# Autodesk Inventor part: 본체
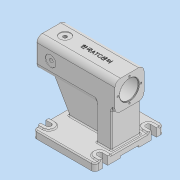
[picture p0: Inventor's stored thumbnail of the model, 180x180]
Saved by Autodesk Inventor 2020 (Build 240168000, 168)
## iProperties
Created: 2024-07
Part Number: 본체
Material: 일반
Document SubType Name: Modeling
Designer: oem
Density: 1 g/cm^3
Appearance: 기본값
Author: oem
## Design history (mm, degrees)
sketch "스케치1"
  geometry: L1 (85, -95)-(-85, -95); L2 (-85, -95)-(-85, 95); L3 (-85, 95)-(85, 95); L4 (85, 95)-(85, -95); 3 further points
  constraints: 8 end point, 2 midpoint, 2 parallel, 1 horizontal, 1 horizontal alignment, 1 perpendicular, 1 vertical alignment
  dimensions: "d0" = 170 distance of L1.start L1.end; "d1" = 190 distance of L1.end L2.end
extrude "돌출1" new body sketch "스케치1" distance "d2" = 20; taper "d3" = 0 deg
sketch "스케치2"
  geometry: L1 (0, 0)-(190, 0) reference; L2 (55, 190)-(135, 190); L3 (135, 190)-(135, 110); L4 (135, 110)-(55, 110); L5 (55, 110)-(55, 190); 4 further points
  constraints: 8 end point, 3 midpoint, 2 parallel, 1 horizontal, 1 perpendicular, 1 vertical alignment
  dimensions: "d4" = 80 distance of L2.end L3.end; "d5" = 80 distance of L2.start L2.end; "d6" = 150 distance from line of L1 point (55, 150)
extrude "돌출2" join sketch "스케치2" distance "d7" = 217; taper "d8" = 0 deg
sketch "스케치3"
  geometry: L1 (85, -95)-(85, 95) reference; L2 (35, -40)-(75, -40); L3 (75, -40)-(75, 40); L4 (75, 40)-(35, 40); L5 (35, 40)-(35, -40); 2 further points
  constraints: 8 end point, 2 parallel, 1 horizontal, 1 horizontal alignment, 1 midpoint, 1 perpendicular
  dimensions: "d9" = 40 distance of L3.end L4.end; "d10" = 80 distance of L2.end L3.end; "d11" = 10 distance between parallel lines of L1 L3
extrude "돌출3" join sketch "스케치3" stored distance "d12" = 217; taper "d13" = 0 deg
node "작업 평면1"
sketch "스케치4"
  geometry: L1 (-50, 0)-(-217, 0) reference; L2 (-202, 0)-(-150.038, -90); L3 (0, -90)-(-170, -90) reference; L4 (-10, -90)-(-10, 0) reference; L5 (-50, -90)-(-10, -90) reference; L6 (-50, -90)-(-50, 0) reference; L7 (-50, 0)-(-217, 0) reference; L8 (-217, 80)-(-217, 0) reference; L9 (0, 80)-(-217, 80) reference; L10 (0, 0)-(0, 80) reference; L11 (0, 0)-(-10, 0) reference; L12 (0, -110)-(-170, -110) reference; L13 (-170, -110)-(-170, -90) reference; L14 (0, -90)-(-170, -90) reference; L15 (0, -110)-(0, -90) reference; 3 further points
  constraints: 2 end point, 2 point on line
  dimensions: "d15" = 15 distance of L1.end L2.start; "d16" = 120 deg angle of L3 L2
extrude "돌출4" join sketch "스케치4" stored distance "d17" = 30; taper "d18" = 0 deg
sketch "스케치5"
  geometry: L1 (-132, 150)-(85, 150); L2 (85, 176)-(-127, 176); L3 (-127, 176)-(-127, 170.5); L4 (-127, 170.5)-(-132, 170.5); L5 (-132, 190)-(-132, 110) reference; L6 (85, 110)-(85, 190) reference; 1 further point
  constraints: 8 end point, 2 midpoint, 2 perpendicular, 2 point on line, 1 horizontal
  dimensions: "d22" = 212 distance of L2.start L2.end; "d25" = 41 diameter of L4 L1; "d26" = 52 diameter of L2 L1
revolve "회전1" sketch "스케치5" stored, may be unused: angle "d27" = 90 deg
sketch "스케치6"
  geometry: L1 (0, 0)-(190, 0) reference; L2 (70, 0)-(120, 0); L3 (120, 0)-(120, 5); L4 (120, 5)-(70, 5); L5 (70, 5)-(70, 0); 5 further points
  constraints: 8 end point, 2 midpoint, 2 parallel, 1 collinear, 1 horizontal, 1 perpendicular, 1 vertical alignment
  dimensions: "d31" = 50 distance of L2.start L2.end; "d32" = 5 distance of L4.end L2.start
extrude "돌출5" cut sketch "스케치6" distance "d33" = 184.25; taper "d34" = 0 deg
sketch "스케치7" dims "d37" = 30
  geometry: L1 (85, -95)-(85, 95) reference; L2 (70, -67)-(70, 67); L3 (85, -82)-(70, -82); L4 (85, 52)-(70, 52); L5 (85, -52)-(70, -52); L6 (85, 82)-(70, 82); L7 (-85, -95)-(85, -95) reference; L8 (0, -95)-(0, 115.42); L9 (-75, 40)-(-75, -40); L10 (-70, -67)-(-70, 67); L11 (-85, -95)-(-85, 95); L12 (-85, -52)-(-70, -52); L13 (-85, -82)-(-70, -82); L14 (-85, 52)-(-70, 52); L15 (-85, 82)-(-70, 82); A1 r 15 centre (70, -67) between (70, -82) and (70, -52); A2 r 15 centre (-70, -67) between (-70, -82) and (-70, -52); 9 further points
  constraints: 26 end point, 14 symmetric about line, 10 point on line, 6 horizontal, 4 point on circle, 3 midpoint, 2 centre point, 2 tangent, 2 vertical, 1 horizontal alignment, 7 other
  dimensions: "d35" = 30 diameter of A1; "d36" = 15 distance from line of L1 L2.start; "d38" = 15 distance from line of L1 L2.end; "d39" = 134 distance of L2.start L2.end
extrude "돌출6" join sketch "스케치7" distance "d40" = 3; taper "d41" = 0 deg
sketch "스케치8"
  geometry: L1 (85, 82)-(70, 82) reference; L2 (70, 52)-(85, 52) reference; L3 (85, 52)-(85, 82) reference; L4 (85, 60)-(70, 60); L5 (70, 74)-(85, 74); L6 (70, -82)-(85, -82) reference; L7 (70, -82)-(85, -82) reference; L8 (85, -82)-(85, -52) reference; L9 (85, -52)-(70, -52) reference; L10 (70, -74)-(85, -74); L11 (85, -60)-(70, -60); L12 (-85, -95)-(85, -95) reference; L13 (0, -95)-(0, 108.744); L14 (-85, 82)-(-70, 82); L15 (-70, 52)-(-85, 52); L16 (-85, 60)-(-70, 60); L17 (-70, 74)-(-85, 74); L18 (-85, 52)-(-85, 82); L19 (-85, -52)-(-70, -52); L20 (-85, -60)-(-70, -60); L21 (-70, -74)-(-85, -74); L22 (-85, -82)-(-85, -52); L23 (-70, -82)-(-85, -82); L24 (-70, -82)-(-85, -82); A1 r 15 centre (70, 67) between (70, 82) and (70, 52) reference; A2 r 7 centre (70, 67) between (70, 74) and (70, 60); A3 r 15 centre (70, -67) between (70, -52) and (70, -82) reference; A4 r 15 centre (70, -67) between (70, -52) and (70, -82) reference; A5 r 7 centre (70, -67) between (70, -60) and (70, -74); A6 r 15 centre (-70, 67) between (-70, 52) and (-70, 82); A7 r 7 centre (-70, 67) between (-70, 60) and (-70, 74); A8 r 7 centre (-70, -67) between (-70, -74) and (-70, -60); A9 r 15 centre (-70, -67) between (-70, -82) and (-70, -52); A10 r 15 centre (-70, -67) between (-70, -82) and (-70, -52); 1 further point
  constraints: 32 end point, 22 symmetric about line, 14 point on circle, 8 point on line, 7 centre point, 1 midpoint, 1 perpendicular, 1 vertical, 8 other
  dimensions: "d42" = 14 distance between parallel lines of L5 L4; "d43" = 14 distance of L10.end L11.start
extrude "돌출7" cut sketch "스케치8" stored distance "d44" = 3; taper "d45" = 0 deg
sketch "스케치9"
  geometry: L1 (0, 80)-(0, 0) reference; L2 (0, 40)-(-177, 40); 2 further points
  constraints: 2 end point, 2 midpoint, 1 coincident, 1 horizontal
  dimensions: "d46" = 177 distance of L2.start L2.end
hole "구멍1" sketch "스케치9" at (-177, 40) diameter "d47" = 10.106; stored, may be unused: countersink angle "d51" = 90 deg, drill point angle "d53" = 118 deg; dims "d48" = 24, "d49" = 30, "d50" = 2, "d52" = 32.3
sketch "스케치10"
  geometry: L1 (0, -12)-(0, 92) reference; L2 (0, 40)-(-177, 40); 1 further point
  constraints: 2 end point, 1 horizontal, 1 midpoint
  dimensions: "d54" = 177 distance of L2.start L2.end
hole "구멍2" sketch "스케치10" at (-177, 40) diameter "d55" = 10.106; stored, may be unused: countersink angle "d59" = 90 deg, drill point angle "d61" = 118 deg; dims "d56" = 24, "d57" = 30, "d58" = 2, "d60" = 32.3
fillet "모깎기1" dims "d62" = 15
fillet "모깎기2" dims "d63" = 3
fillet "모깎기3" dims "d64" = 3
fillet "모깎기4" dims "d65" = 3
fillet "모깎기5" dims "d66" = 3
fillet "모깎기6" dims "d67" = 3
fillet "모깎기7" dims "d68" = 3
fillet "모깎기8" dims "d69" = 3
sketch "스케치11"
  geometry: L1 (95, 150)-(95, 182); C1 r 27 at (95, 150) reference; 1 further point
  constraints: 2 end point, 1 vertical
  dimensions: "d70" = 32 distance of L1.start L1.end
hole "구멍3" sketch "스케치11" at (95, 182) diameter "d71" = 4.917; stored, may be unused: countersink angle "d75" = 90 deg, drill point angle "d77" = 118 deg; dims "d72" = 12, "d73" = 30, "d74" = 2, "d76" = 14
fillet "모깎기9" dims "d81" = 3
fillet "모깎기10" dims "d82" = 10
fillet "모깎기11" dims "d83" = 3
sketch "스케치12"
  geometry: L1 (0, 104)-(0, 110) reference; 2 further points
  constraints: 1 horizontal alignment, 1 other
  dimensions: "d84" = 90 distance from line of L1 point (-90, 25)
feature "엠보싱1" sketch "스케치12" dims "d85" = 0.5, "d86" = 0
sketch "스케치13"
  geometry: L1 (85, 176)-(-127, 176) reference; L2 (83, 176)-(85, 177.155); L3 (85, 190)-(85, 175) reference; L4 (50.104, 150)-(120.269, 150); L5 (85, 125)-(85, 175) reference; L6 (-129, 190)-(-129, 175) reference; L7 (-129, 190)-(85, 190) reference; L8 (85, 190)-(85, 175) reference; L9 (85, 175)-(-129, 175) reference; 3 further points
  constraints: 4 end point, 2 midpoint, 2 point on line, 1 horizontal, 1 horizontal alignment
  dimensions: "d87" = 2 horizontal distance of L2.start L2.end; "d88" = 30 deg angle of L1 L2
revolve "회전2" sketch "스케치13" stored, may be unused: angle "d89" = 90 deg
fillet "모깎기12" dims "d90" = 1
fillet "모깎기13" dims "d91" = 2
chamfer "모따기2" distance "d92" = 1; stored, may be unused: second distance "d93" = 2, angle "d94" = 45 deg
node "솔리드1"
mirror "미러1"
pattern_circular "원형 패턴1" dims angle "d79" = 360 deg
node "투영된 루프1"
node "투영된 루프2"
node "투영된 루프3"
node "투영된 루프4"
feature "A9D066F2-1C7D-4E18-AEED-F7BC21143FA4" dims "d47" = 10.106, "d48" = 24, "d49" = 30, "d50" = 2, "d51" = 90 deg, "d52" = 32.3, "d53" = 118 deg
other parameters: "d19" = 41, "d20" = 52
